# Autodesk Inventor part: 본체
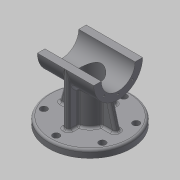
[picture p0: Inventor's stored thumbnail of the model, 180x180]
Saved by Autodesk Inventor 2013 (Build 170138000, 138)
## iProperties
Created: 2015-12
Part Number: 본체
Material: 일반
Document SubType Name: Modeling
Designer: mduedu
Density: 2.71 g/cm^3
Author: mduedu
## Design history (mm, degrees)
sketch "스케치1"
  geometry: C1 r 55 at (0, 0); 1 further point
  constraints: 1 centre point, 1 coincident
  dimensions: "d124" = 110 diameter of C1
extrude "돌출1" new body sketch "스케치1" distance "d3" = 10; taper "d4" = 0 deg
sketch "스케치2"
  geometry: C1 r 32.5 at (80, 0); 1 further point
  constraints: 1 centre point, 1 horizontal alignment
  dimensions: "d5" = 65 diameter of C1; "d125" = 80 distance of C1.centre point (0, 0)
extrude "돌출2" join sketch "스케치2" stored distance "d7" = 75; taper "d8" = 0 deg
sketch "스케치3"
  geometry: C1 r 20 at (0, 0); 1 further point
  constraints: 1 centre point, 1 coincident
  dimensions: "d154" = 40 diameter of C1
extrude "돌출3" new body sketch "스케치3" stored distance "d12" = 75; taper "d13" = 0 deg
feature "결합1"
  node "솔리드2"
sketch "스케치19"
  geometry: L1 (0, 55)-(10, 55) reference; L2 (10, 55)-(10, 20) reference; L3 (10, 20)-(54.383, 20) reference; L4 (54.383, -20)-(10, -20) reference; L5 (10, -20)-(10, -55) reference; L6 (10, -55)-(0, -55) reference; L7 (0, -55)-(0, 55) reference; L8 (10, -32.5)-(80, -32.5); A1 r 32.5 centre (80, 0) between (54.383, -20) and (54.383, 20) reference; 1 further point
  constraints: 2 end point, 1 horizontal, 1 point on circle, 1 point on line, 1 tangent
feature "리브3" sketch "스케치19" dims "d161" = 1, "d162" = 8, "d163" = 0, "d164" = 0, "d165" = 1, "d166" = 1
sketch "스케치20"
  geometry: L1 (-37.5, 47.5)-(-37.5, 112.5) reference; L2 (-37.5, 112.5)-(37.5, 112.5) reference; L3 (37.5, 112.5)-(37.5, 47.5) reference; L4 (37.5, 47.5)-(20, 47.5) reference; L5 (20, 47.5)-(20, 10) reference; L6 (20, 10)-(55, 10) reference; L7 (55, 10)-(55, 0) reference; L8 (55, 0)-(-55, 0) reference; L9 (-55, 0)-(-55, 10) reference; L10 (-55, 10)-(-20, 10) reference; L11 (-20, 10)-(-20, 47.5) reference; L12 (-20, 47.5)-(-37.5, 47.5) reference; L13 (27.5, 47.5)-(37.548, 10); 1 further point
  constraints: 2 end point, 2 point on line
  dimensions: "d167" = 10 distance from line of L13.start L3; "d168" = 105 deg angle of L13 L6
feature "리브4" sketch "스케치20" dims "d169" = 1, "d170" = 8, "d171" = 0, "d172" = 0, "d173" = 1, "d174" = 1
fillet "모깎기14" dims "d175" = 3
fillet "모깎기15" dims "d176" = 3
fillet "모깎기7" dims "d41" = 3
hole "구멍2" diameter "d44" = 45; stored, may be unused: countersink angle "d48" = 90 deg, drill point angle "d50" = 118 deg; dims "d42" = 10, "d43" = 10, "d45" = 6, "d46" = 4, "d47" = 2, "d49" = 8
sketch "스케치7" dims "d52" = 26.5
  geometry: L1 (0, 0)-(32.5, 0); L2 (0, 0)-(0, 32.5); A1 r 32.5 centre (0, 0) between (32.5, 0) and (0, 32.5) reference; 3 further points
  constraints: 4 end point, 2 point on circle, 1 coincident, 1 horizontal, 1 point on line, 1 vertical alignment, 2 other
  dimensions: "d51" = 90 deg angle of L2 L1
hole "구멍3" sketch "스케치7" at (0, 26.5) diameter "d54" = 2.459; stored, may be unused: countersink angle "d58" = 90 deg, drill point angle "d60" = 118 deg; dims "d55" = 8, "d56" = 4, "d57" = 2, "d59" = 10
sketch "스케치9"
  geometry: L1 (-75, 82.5)-(75, 82.5); L2 (75, 82.5)-(75, 0); L3 (75, 0)-(-75, 0); L4 (-75, 0)-(-75, 82.5); C1 r 32.5 at (0, 0) reference; 2 further points
  constraints: 8 end point, 2 parallel, 1 coincident, 1 horizontal, 1 midpoint, 1 perpendicular
  dimensions: "d71" = 50 distance edge to line of C1 L1; "d116" = 150 distance between parallel lines of L2 L4
extrude "돌출5" cut sketch "스케치9" stored distance "d73" = 0; taper "d74" = 0 deg
node "작업 평면1"
sketch "스케치10"
  geometry: C1 r 15 at (0, 0); 1 further point
  constraints: 1 centre point, 1 coincident
  dimensions: "d156" = 30 diameter of C1
extrude "돌출6" cut sketch "스케치10" stored distance "d78" = 50; taper "d79" = 0 deg
sketch "스케치11"
  geometry: 2 further points
  constraints: 1 coincident
hole "구멍4" sketch "스케치11" at (0, 0) diameter "d81" = 12; stored, may be unused: countersink angle "d85" = 90 deg, drill point angle "d87" = 118 deg; dims "d82" = 8, "d83" = 30, "d84" = 10, "d86" = 10
sketch "스케치12"
  geometry: C1 r 10 at (0, 0); 1 further point
  constraints: 1 centre point, 1 coincident
  dimensions: "d88" = 20 diameter of C1
extrude "돌출7" cut sketch "스케치12" distance "d89" = 10; taper "d90" = 0 deg
chamfer "모따기1" distance "d91" = 1; stored, may be unused: second distance "d92" = 2, angle "d93" = 45 deg
sketch "스케치18" dims "d141" = 90
  geometry: C1 r 52 at (0, 0) reference; 2 further points
  constraints: 2 vertical alignment, 1 coincident, 2 other
hole "구멍8" sketch "스케치18" at (0, 45) diameter "d142" = 9; stored, may be unused: countersink angle "d146" = 90 deg, drill point angle "d148" = 118 deg; dims "d143" = 6, "d144" = 4, "d145" = 2, "d147" = 8
node "솔리드1"
mirror "대칭8"
mirror "대칭9"
pattern_circular "원형 패턴1" dims angle "d62" = 360 deg
mirror "대칭3"
pattern_circular "원형 패턴2" dims angle "d150" = 360 deg
node "절단 모서리 투영1"
node "절단 모서리 투영2"
